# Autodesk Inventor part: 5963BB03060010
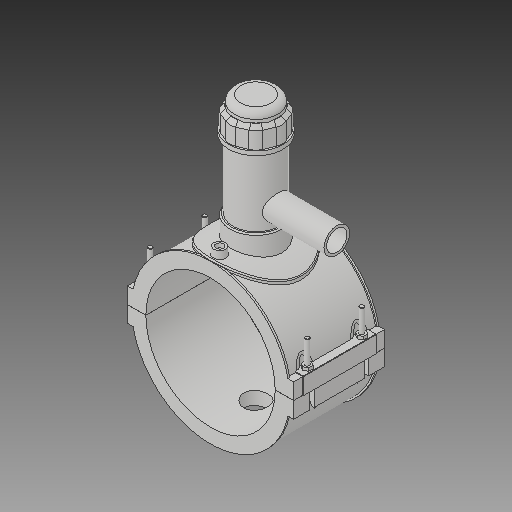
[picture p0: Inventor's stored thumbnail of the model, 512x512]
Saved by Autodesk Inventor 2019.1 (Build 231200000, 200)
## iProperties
Created: 2017-07
Part Number: 5963BB03060010
Material: Generic
Description: PLASSON TAPPING SADDLE 6''IPS x 1''IPS
Document SubType Name: Modeling
Designer: KIM
Mass: 1712.7 g
Surface Area: 2671.49 cm^2
Volume: 1712.7 cm^3
Density: 1 g/cm^3
Appearance: Default
Author: KIM
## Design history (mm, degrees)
derived "5963B.ipt"
feature "Solid1::5963B.ipt"
feature "Solid2::5963B.ipt"
feature "Solid4::5963B.ipt"
feature "Solid5::5963B.ipt"
tag "TaggingFeature1"
body "Solid1"
body "Solid2"
other parameters: "d_" = 168, "B_" = 215.9, "L_" = 118.11, "d_t" = 6, "H_2" = 177.038, "H_1" = 65.024, "d_1" = 33.3, "H_" = 104.902, "d1" = 201.6, "d148" = 2.52, "d160" = 2.52, "d169" = 3.2805, "d192" = 6.1236, "d0" = 168, "d2" = 215.9, "d3" = 42, "d4" = 118.11, "d5" = 0, "d6" = 0.1, "d8" = 0, "d19" = 6, "d20" = 6, "d21" = 70.866, "d23" = 0, "d24" = 35.433, "d26" = 0, "d29" = 3, "d30" = 56, "d31" = 6, "d32" = 0, "d33" = 0, "d34" = 0.6, "d40" = 104.832, "d41" = 117.6, "d43" = 0, "d45" = 0, "d47" = 171.666, "d70" = 15, "d72" = 0, "d73" = 6, "d75" = 5, "d76" = 0, "d77" = 8.4, "d78" = 114, "d79" = 15, "d80" = 47.244, "d82" = 5 deg, "d84" = 4, "d85" = 14, "d86" = 0, "d87" = 3, "d88" = 0, "d89" = 1, "d90" = 1, "d91" = 94.488, "d92" = 0, "d93" = 0.5, "d94" = 88.42105, "d96" = 205.632, "d97" = 2.3622, "d98" = 0, "d102" = 1.68, "d120" = 140 deg, "d121" = 24.228, "d122" = 20 deg, "d123" = 403.2, "d124" = 120.96, "d126" = 0, "d143" = 173.04, "d145" = 25.84615, "d149" = 2.52, "d150" = 28.43077, "d153" = 118.11, "d154" = 0, "d156" = 100.8, "d157" = 160 deg, "d159" = 6.72, "d161" = 2.52, "d162" = 70.866, "d163" = 0, "d164" = 84, "d167" = 16.8, "d168" = 98.34146, "d170" = 3.2805, "d172" = 0, "d173" = 1, "d175" = 84, "d176" = 20 deg, "d177" = 11.76, "d178" = 33.6, "d180" = 0, "d183" = 13.44, "d184" = 9.408, "d185" = 38.38575, "d186" = 38.38575, "d187" = 100.8, "d188" = 10.08, "d189" = 11.76, "d190" = 0, "d191" = 151.2, "d193" = 6.1236, "d194" = 4.13385, "d195" = 90 deg, "d197" = 0, "d199" = 0, "d200" = 16.8, "d202" = 0, "d203" = 177.038, "d204" = 67.032, "d205" = 49.392, "d206" = 59.976, "d207" = 132.7785, "d208" = 138.08964, "d209" = 164.64534, "d210" = 60.6816, "d211" = 70.56, "d212" = 56.448, "d213" = 43.5366, "d216" = 0, "d217" = 16.8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
